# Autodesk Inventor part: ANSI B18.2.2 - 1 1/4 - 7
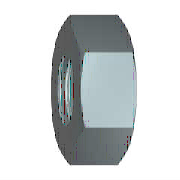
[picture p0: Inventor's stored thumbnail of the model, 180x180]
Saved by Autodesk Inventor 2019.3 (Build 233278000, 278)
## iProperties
Created: 2018-01
Part Number: ANSI B18.2.2 - 1 1/4 - 7
Material: Steel, Mild
Description: Hex Nuts (Inch Series) Heavy Hex Nut
Document SubType Name: Modeling
Standard: ANSI B18.2.2
Designer: u1426
Standard Revision: 2010
Standards Organization: ANSI
Language: en-US
Size Designation: 1 1/4 - 7
Categories: <MemberInstance><Categories><Category DisplayName="Fasteners" InternalName="e4da775c-781d-43d5-af7c-5136215cf5a6" Mnemonic="FSTN"><Category DisplayName="Nuts" I
Density: 7.85 g/cm^3
Appearance: Semi-Polished
IsCustomPart: 0
Author: u1426
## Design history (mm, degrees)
sketch "Sketch1"
  geometry: L1 (-29.329, 0)-(-14.665, 25.4); L2 (-14.665, 25.4)-(14.665, 25.4); L3 (14.665, 25.4)-(29.329, 0); L4 (29.329, 0)-(14.665, -25.4); L5 (14.665, -25.4)-(-14.665, -25.4); L6 (-14.665, -25.4)-(-29.329, 0); 2 further points
  constraints: 12 end point, 1 coincident, 1 horizontal, 11 other
  dimensions: "d0" = 58.65879 distance of L3.end L1.start (= 1.1547 x SW)
extrude "Body" new body sketch "Sketch1" distance "d1" = 30.9626 (= KOH); taper "d2" = 0 deg
sketch "Sketch2"
  geometry: L1 (0, 14.665)-(0, 29.329) reference; L2 (0, 29.329)-(30.963, 29.329) reference; L3 (30.963, 14.665)-(30.963, 29.329) reference; L4 (-6.193, 0)-(37.155, 0) reference; L5 (1.832, 29.329)-(0, 25.4); L6 (29.13, 29.329)-(30.963, 25.4)
  constraints: 4 end point, 4 point on line
  dimensions: "d3" = 25 deg angle of L1 L5 (= ANG1); "d4" = 25 deg angle of L3 L6 (= ANG2); "d5" = 50.8 diameter of L5.end L4 (= SW0); "d6" = 50.8 diameter of L6.end L4 (= SW01)
revolve "Chamfer1" sketch "Sketch2" stored, may be unused: angle "d7" = 90 deg
sketch "Sketch3"
  geometry: A1 r 25.4 centre (0, 0) between (-12.7, -21.997) and (12.7, -21.997) reference; 1 further point
  constraints: 1 coincident
hole "Thread" sketch "Sketch3" at (0, 0) diameter "d25" = 27.813; stored, may be unused: countersink angle "d29" = 82 deg, drill point angle "d31" = 118 deg; dims "d26" = 6, "d27" = 4, "d28" = 2, "d30" = 8
workaxis "Work Axis1"
workplane "Work Plane1"
body "Solid1"
chamfer "Chamfer2" distance "d8" = 1.96402 (= -0.5 x GD1 + 0.5 x NND); stored, may be unused: angle "d9" = 30 deg, second distance "d40" = 1.96402 (= -0.5 x GD1 + 0.5 x NND)
chamfer "Chamfer3" distance "d10" = 1.96402 (= -0.5 x GD1 + 0.5 x NND); stored, may be unused: angle "d11" = 30 deg, second distance "d41" = 1.96402 (= -0.5 x GD1 + 0.5 x NND)
other parameters: "ANG1" = 25 deg [user parameter; used in 1 equation term], "ANG2" = 25 deg [user parameter; used in 1 equation term], "NND" = 31.75 [user parameter; used in 4 equation terms], "KOH" = 30.9626 [user parameter; used in 1 equation term], "SW" = 50.8 [user parameter; used in 4 equation terms], "SW0" = 50.8 (= SW) [user parameter; used in 1 equation term], "SW01" = 50.8 (= SW) [user parameter; used in 1 equation term], "GD1" = 27.82196 (computed from THREADDIA, PTC, TOA) [user parameter; used in 4 equation terms], "d13" = 0, "d14" = 0, "d39" = 0, "d42" = 0, "THREADDIA" = 31.75 [user parameter; used in 1 equation term], "TOA" = 30 deg [user parameter; used in 1 equation term], "PTC" = 3.62857 (computed from TPU) [user parameter; used in 1 equation term], "E0" = 58.674 (= 1.155 x SW) [user parameter]
